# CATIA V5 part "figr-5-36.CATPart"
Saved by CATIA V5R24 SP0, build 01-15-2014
Part number: Part1
Bounding box of the stored display mesh (mm): x -80 to 80, y -60 to 60, z 0 to 120
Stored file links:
  D:\KAVITA\CATIA V5-6R2014 Project_ Kavita\CATIA V5-6R2014_partfiles\Partfiles\c05_catia_v5-6r2014_prt\figr-5-36.CATPart
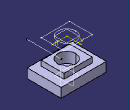
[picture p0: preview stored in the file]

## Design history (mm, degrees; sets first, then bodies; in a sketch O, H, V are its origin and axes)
Set1
  Plane1: type Offset, RefPlane xy-plane, Offset 120
Body1 (main body)
  Sketch1 on xy-plane, origin (0, 0, 0), H (1, 0, 0), V (0, 1, 0)
    line L1 (80, 60) -> (80, -60)
    line L2 (80, -60) -> (-80, -60)
    line L3 (-80, -60) -> (-80, 60)
    line L4 (-80, 60) -> (80, 60)
    circle A1 centre (0, 0) radius 31.6228
    line L5 (50, 40) -> (50, -40)
    line L6 (50, -40) -> (-50, -40)
    line L7 (-50, -40) -> (-50, 40)
    line L8 (-50, 40) -> (50, 40)
    vertical: L1 V, L3 V, L5 V, L7 V
    horizontal: L2 H, L4 H, L6 H, L8 H
    equidistance: L1 L3 O, L2 L4 O, L5 L7 O, L6 L8 O
  MultiPad1: profile Sketch1, domains (length 51; length 33; length 14)
  Sketch2 on Plane1, origin (0, 0, 120), H (1, 0, 0), V (0, 1, 0)
    projected line E1 (50, 40) -> (-50, 40) from edge [face of MultiPad1 | face of MultiPad1]
    projected line E2 (-50, 40) -> (-50, -40) from edge [face of MultiPad1 | face of MultiPad1]
    projected line E3 (-50, -40) -> (50, -40) from edge [face of MultiPad1 | face of MultiPad1]
    projected line E4 (50, -40) -> (50, 40) from edge [face of MultiPad1 | face of MultiPad1]
    projected circle E5 centre (0, 0) radius 31.6228 from edge [face of MultiPad1 | face of MultiPad1]
    projected line E6 (80, -60) -> (80, 60) from edge [face of MultiPad1 | face of MultiPad1]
